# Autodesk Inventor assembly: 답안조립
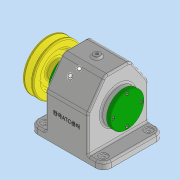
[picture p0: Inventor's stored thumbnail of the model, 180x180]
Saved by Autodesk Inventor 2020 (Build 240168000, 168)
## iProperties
Created: 2022-12
Part Number: 답안조립
Document SubType Name: Assembly
Designer: 1강의실14
Author: 1강의실14
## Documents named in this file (15)
- C:\Users\1강의실14\Desktop\721206V1013\답안조립.iam
- C:\Users\1강의실14\Desktop\721206V1013\본체.ipt
- C:\Users\1강의실14\Desktop\721206V1013\V-벨트풀리.ipt
- C:\Users\1강의실14\Desktop\721206V1013\뒤커버.ipt
- C:\Users\1강의실14\Desktop\721206V1013\멈춤나사 - M4x10.ipt
- C:\Users\1강의실14\Desktop\721206V1013\베어링 6203.ipt
- C:\Users\1강의실14\Desktop\721206V1013\볼트 M3 x 8.ipt
- C:\Users\1강의실14\Desktop\721206V1013\볼트 M3 x 10.ipt
- C:\Users\1강의실14\Desktop\721206V1013\스퍼기어.ipt
- C:\Users\1강의실14\Desktop\721206V1013\앞커버.ipt
- C:\Users\1강의실14\Desktop\721206V1013\오일 실 17 x 32 x 8.ipt
- C:\Users\1강의실14\Desktop\721206V1013\축.ipt
- C:\Users\1강의실14\Desktop\721206V1013\칼라.ipt
- C:\Users\1강의실14\Desktop\721206V1013\키 - 5 x 5 x 18.ipt
- C:\Users\1강의실14\Desktop\721206V1013\키 - 6 x 6 x 22.ipt
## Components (9 placed, 3 different names)
1. V-벨트풀리:1
2. ISO 4762 M3 x 8:1 — 각도:1
3. ISO 4762 M3 x 8:2
4. ISO 4762 M3 x 8:3
5. ISO 4762 M3 x 8:4
6. ISO 4762 M3 x 10:1 — 각도:2
7. ISO 4762 M3 x 10:2
8. ISO 4762 M3 x 10:3
9. ISO 4762 M3 x 10:4
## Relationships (2: Angle 2)
- 각도:1 [Angle]: ISO 4762 M3 x 8:1
- 각도:2 [Angle]: ISO 4762 M3 x 10:1
